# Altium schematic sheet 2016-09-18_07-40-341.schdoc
size 309 x 119 mm; SheetNumber: 1; SheetTotal: 1
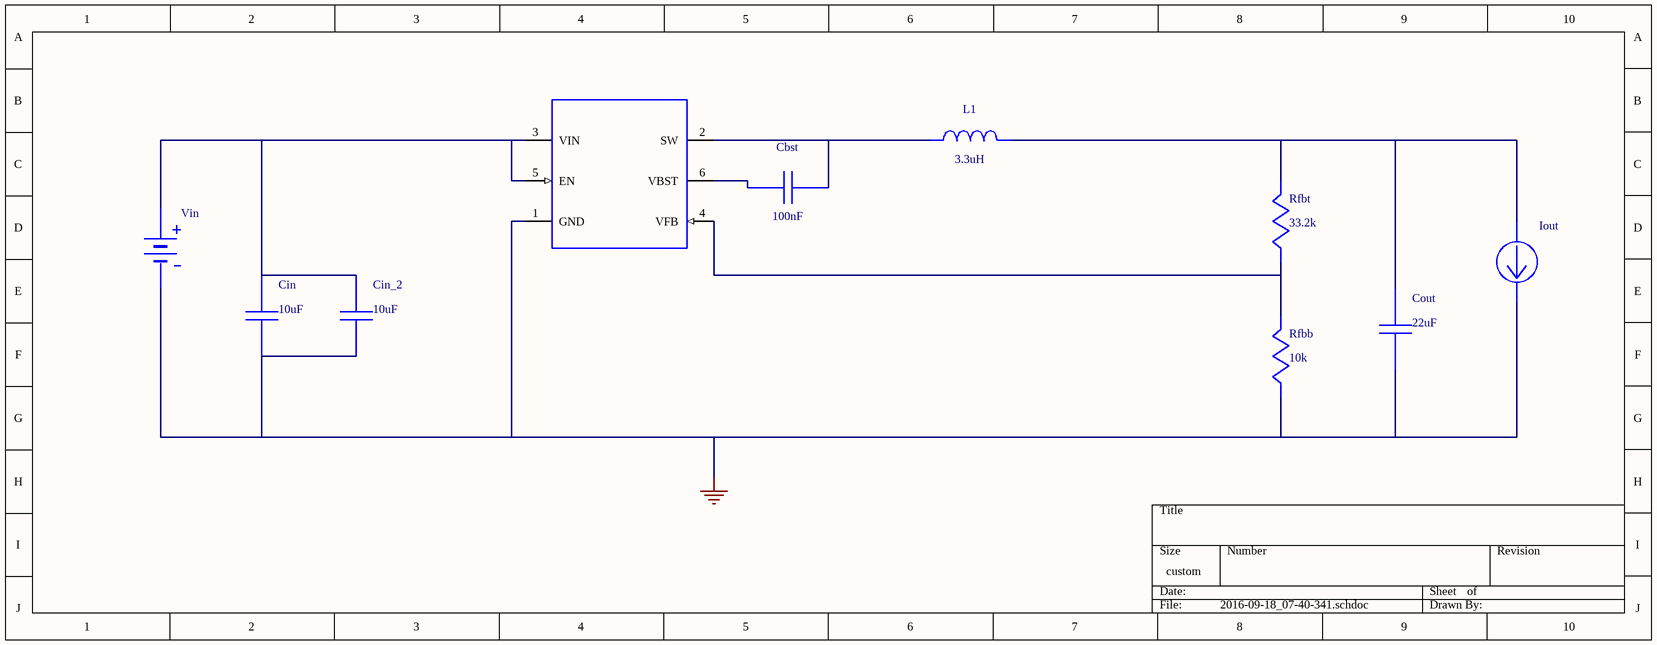
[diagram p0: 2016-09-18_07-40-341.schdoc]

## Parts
Cbst  value 100nF  (hidden comment: 08053C104KAT2A)
Cin  value 10uF  (hidden comment: GRM21BR61C106KE15L)
Cin_2  value 10uF  (hidden comment: GRM21BR61C106KE15L)
Cout  value 22uF  (hidden comment: GRM31CR60J226KE19L)
Iout  WB_CURRENT_LOAD  (value not drawn)
L1  value 3.3uH  (hidden comment: SRR4028-3R3Y)
Rfbb  value 10k  (hidden comment: CRCW040210K0FKED)
Rfbt  value 33.2k  (hidden comment: CRCW040233K2FKED)
U1  TPS562200DDCR  (value not drawn)
Vin  WB_BATTERY  (value not drawn)

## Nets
0: Cin.2 Cin_2.2 Cout.2 Iout.2(-) Rfbb.2 U1.1(GND) Vin.2(-)
NetCbst_1: Cbst.1 L1.1 U1.2(SW)
NetCbst_2: Cbst.2 U1.6(VBST)
NetCin_1: Cin.1 Cin_2.1 U1.3(VIN) U1.5(EN) Vin.1(+)
NetCout_1: Cout.1 Iout.1(+) L1.2 Rfbt.1
NetRfbb_1: Rfbb.1 Rfbt.2 U1.4(VFB)

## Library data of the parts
Cbst = 08053C104KAT2A: Manufacturer Name: AVX
Cin Cin_2 = GRM21BR61C106KE15L: GRM21BR61C106KE1; Manufacturer Name: MuRata
Cout = GRM31CR60J226KE19L: GRM31CR60J226KE1; Manufacturer Name: MuRata
L1 = SRR4028-3R3Y: Manufacturer Name: Bourns
Rfbb = CRCW040210K0FKED: Manufacturer Name: Vishay-Dale
Rfbt = CRCW040233K2FKED: Manufacturer Name: Vishay-Dale
U1 = TPS562200DDCR: Manufacturer Name: Texas Instruments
